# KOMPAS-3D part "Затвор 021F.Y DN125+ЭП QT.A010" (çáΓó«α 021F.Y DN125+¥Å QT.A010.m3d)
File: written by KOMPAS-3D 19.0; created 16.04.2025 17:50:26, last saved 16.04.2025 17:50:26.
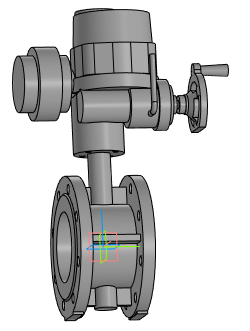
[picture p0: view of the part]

Document properties: Полное имя файла: Затвор 021F.Y DN125+ЭП QT.A010.a3d

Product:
- Part/product: Затвор 021F.Y DN125+ЭП QT.A010
    Масса: 55.985

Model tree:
1. Операция без истории:1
